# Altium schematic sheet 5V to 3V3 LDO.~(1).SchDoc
size A3; SheetNumber: 12; SheetTotal: 13
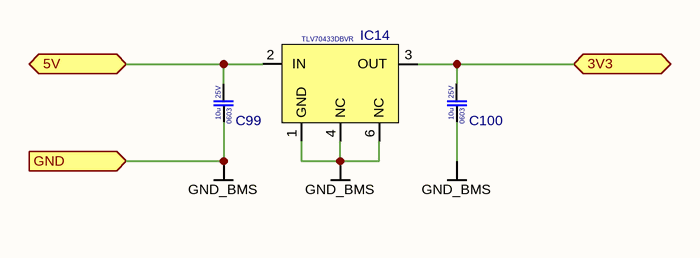
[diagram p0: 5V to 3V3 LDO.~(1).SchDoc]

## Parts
C99  Voltage Rating: 25V  Case Code (Imperial): 0603  Capacitance: 10u  [CAP 0603]  (hidden comment: CL10A106MA8NRNC)
C100  Voltage Rating: 25V  Case Code (Imperial): 0603  Capacitance: 10u  [CAP 0603]  (hidden comment: CL10A106MA8NRNC)
IC14  TLV70433DBVR  [SOT-23-5]

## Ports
3V3 (bidir, see BMS[6B]), 5V (bidir, see BMS[5B]), GND (in, see BMS[5B], BAT+ to 5V1 STEP-DOWN[3C], BQ76952 BMS[1D], MCU[1C])

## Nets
GND_BMS: C99.1 C100.1 IC14.1(GND) IC14.4(NC) IC14.6(NC) ; port GND
3V3: C100.2 IC14.3(OUT) ; port 3V3
5V: C99.2 IC14.2(IN) ; port 5V

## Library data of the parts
C99 C100 = CL10A106MA8NRNC: Cap 10uF 25V 0603 X5R; Manufacturer: Samsung
IC14 = TLV70433DBVR: LDO 24Vin 3.3Vout 150mA SOT-23-5; Manufacturer: Texas Instruments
